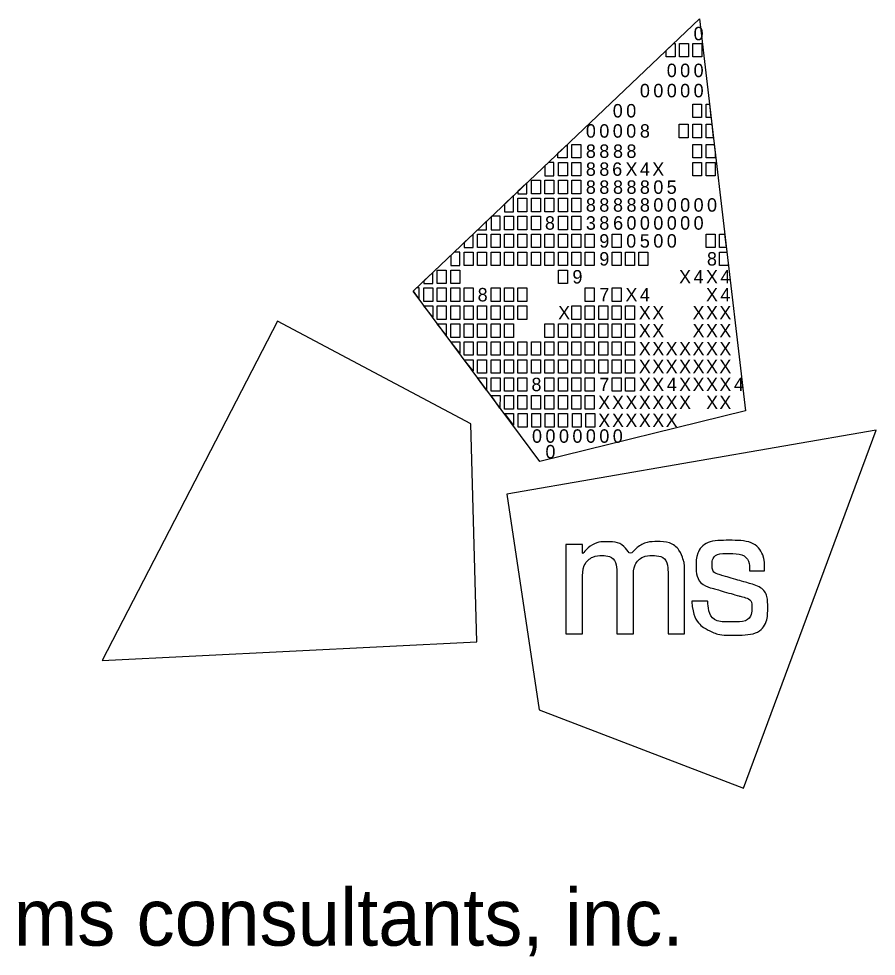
# Model space of a CAD drawing. Extents: x -19 to 34, y 0 to 22.
# Drawn here: x 32.134 to 33.186, y 2.936 to 4.086 of the extents above; entities that cross this region are included whole.
import ezdxf

# ---------------------------------------------------------------- set-up
doc = ezdxf.new("R2010")
doc.units = 0
doc.layers.add('SH_Border', color=7, linetype='Continuous')
doc.layers.add('SH_Data', color=7, linetype='Continuous')

msp = doc.modelspace()

# ---------------------------------------------------------------- linework, layer by layer
at = {"layer": 'SH_Border'}
for p, q in [((32.6175, 3.7519), (32.9688, 4.0861)), ((32.9688, 4.0861), (32.9688, 4.0861)), ((32.9688, 4.0861), (33.0253, 3.6052)), ((32.773, 3.543), (32.6175, 3.7519)), ((33.0253, 3.6052), (32.773, 3.543))]:
    msp.add_line(p, q, dxfattribs=at)
for points in [[(32.9279, 4.0472), (32.9369, 4.0558), (32.9389, 4.0558), (32.9389, 4.0393), (32.9279, 4.0393)], [(32.9444, 4.0558), (32.9554, 4.0558), (32.9554, 4.0393), (32.9444, 4.0393)], [(32.9609, 4.0558), (32.9719, 4.0558), (32.9719, 4.0393), (32.9609, 4.0393)], [(32.9606, 3.9815), (32.9716, 3.9815), (32.9716, 3.965), (32.9606, 3.965)], [(32.9771, 3.9815), (32.9811, 3.9815), (32.983, 3.965), (32.9771, 3.965)], [(32.9441, 3.9567), (32.9551, 3.9567), (32.9551, 3.9402), (32.9441, 3.9402)], [(32.9606, 3.9567), (32.9716, 3.9567), (32.9716, 3.9402), (32.9606, 3.9402)], [(32.9771, 3.9567), (32.984, 3.9567), (32.9859, 3.9402), (32.9771, 3.9402)], [(32.7953, 3.9211), (32.8064, 3.9316), (32.8064, 3.9154), (32.7953, 3.9154)], [(32.8123, 3.9319), (32.8233, 3.9319), (32.8233, 3.9154), (32.8123, 3.9154)], [(32.9606, 3.9319), (32.9716, 3.9319), (32.9716, 3.9154), (32.9606, 3.9154)], [(32.9771, 3.9319), (32.9869, 3.9319), (32.9881, 3.9218), (32.9881, 3.9154), (32.9771, 3.9154)], [(32.7958, 3.9099), (32.8068, 3.9099), (32.8068, 3.8934), (32.7958, 3.8934)], [(32.8123, 3.9099), (32.8233, 3.9099), (32.8233, 3.8934), (32.8123, 3.8934)], [(32.9606, 3.9099), (32.9716, 3.9099), (32.9716, 3.8934), (32.9606, 3.8934)], [(32.9771, 3.9099), (32.9881, 3.9099), (32.9881, 3.8934), (32.9771, 3.8934)], [(32.7627, 3.8879), (32.7737, 3.8879), (32.7737, 3.8714), (32.7627, 3.8714)], [(32.7793, 3.8879), (32.7903, 3.8879), (32.7903, 3.8714), (32.7793, 3.8714)], [(32.7958, 3.8879), (32.8068, 3.8879), (32.8068, 3.8714), (32.7958, 3.8714)], [(32.8123, 3.8879), (32.8233, 3.8879), (32.8233, 3.8714), (32.8123, 3.8714)], [(32.7462, 3.8659), (32.7572, 3.8659), (32.7572, 3.8494), (32.7462, 3.8494)], [(32.7627, 3.8659), (32.7737, 3.8659), (32.7737, 3.8494), (32.7627, 3.8494)], [(32.7793, 3.8659), (32.7903, 3.8659), (32.7903, 3.8494), (32.7793, 3.8494)], [(32.7958, 3.8659), (32.8068, 3.8659), (32.8068, 3.8494), (32.7958, 3.8494)], [(32.8123, 3.8659), (32.8233, 3.8659), (32.8233, 3.8494), (32.8123, 3.8494)], [(32.7297, 3.8439), (32.7407, 3.8439), (32.7407, 3.8273), (32.7297, 3.8273)], [(32.7462, 3.8439), (32.7572, 3.8439), (32.7572, 3.8273), (32.7462, 3.8273)], [(32.7627, 3.8439), (32.7737, 3.8439), (32.7737, 3.8273), (32.7627, 3.8273)], [(32.7958, 3.8439), (32.8068, 3.8439), (32.8068, 3.8273), (32.7958, 3.8273)], [(32.8123, 3.8439), (32.8233, 3.8439), (32.8233, 3.8273), (32.8123, 3.8273)], [(32.6967, 3.8218), (32.7077, 3.8218), (32.7077, 3.8053), (32.6967, 3.8053)], [(32.7132, 3.8218), (32.7242, 3.8218), (32.7242, 3.8053), (32.7132, 3.8053)], [(32.7297, 3.8218), (32.7407, 3.8218), (32.7407, 3.8053), (32.7297, 3.8053)], [(32.7462, 3.8218), (32.7572, 3.8218), (32.7572, 3.8053), (32.7462, 3.8053)], [(32.7627, 3.8218), (32.7737, 3.8218), (32.7737, 3.8053), (32.7627, 3.8053)], [(32.7793, 3.8218), (32.7903, 3.8218), (32.7903, 3.8053), (32.7793, 3.8053)], [(32.7958, 3.8218), (32.8068, 3.8218), (32.8068, 3.8053), (32.7958, 3.8053)], [(32.8123, 3.8218), (32.8233, 3.8218), (32.8233, 3.8053), (32.8123, 3.8053)], [(32.8288, 3.8218), (32.8398, 3.8218), (32.8398, 3.8053), (32.8288, 3.8053)], [(32.8618, 3.8218), (32.8728, 3.8218), (32.8728, 3.8053), (32.8618, 3.8053)], [(32.9771, 3.8218), (32.9881, 3.8218), (32.9881, 3.8053), (32.9771, 3.8053)], [(32.9935, 3.8218), (32.9998, 3.8218), (33.0018, 3.8053), (32.9935, 3.8053)], [(32.6802, 3.7998), (32.6912, 3.7998), (32.6912, 3.7833), (32.6802, 3.7833)], [(32.6967, 3.7998), (32.7077, 3.7998), (32.7077, 3.7833), (32.6967, 3.7833)], [(32.7132, 3.7998), (32.7242, 3.7998), (32.7242, 3.7833), (32.7132, 3.7833)], [(32.7297, 3.7998), (32.7407, 3.7998), (32.7407, 3.7833), (32.7297, 3.7833)], [(32.7462, 3.7998), (32.7572, 3.7998), (32.7572, 3.7833), (32.7462, 3.7833)], [(32.7627, 3.7998), (32.7737, 3.7998), (32.7737, 3.7833), (32.7627, 3.7833)], [(32.7793, 3.7998), (32.7903, 3.7998), (32.7903, 3.7833), (32.7793, 3.7833)], [(32.7958, 3.7998), (32.8068, 3.7998), (32.8068, 3.7833), (32.7958, 3.7833)], [(32.8123, 3.7998), (32.8233, 3.7998), (32.8233, 3.7833), (32.8123, 3.7833)], [(32.8288, 3.7998), (32.8398, 3.7998), (32.8398, 3.7833), (32.8288, 3.7833)], [(32.8618, 3.7998), (32.8728, 3.7998), (32.8728, 3.7833), (32.8618, 3.7833)], [(32.8783, 3.7998), (32.8893, 3.7998), (32.8893, 3.7833), (32.8783, 3.7833)], [(32.8947, 3.7998), (32.9057, 3.7998), (32.9057, 3.7833), (32.8947, 3.7833)], [(32.9935, 3.7998), (33.0024, 3.7998), (33.0044, 3.7833), (32.9935, 3.7833)], [(32.6471, 3.7778), (32.6581, 3.7778), (32.6581, 3.7613), (32.6471, 3.7613)], [(32.6637, 3.7778), (32.6747, 3.7778), (32.6747, 3.7613), (32.6637, 3.7613)], [(32.7958, 3.7778), (32.8068, 3.7778), (32.8068, 3.7613), (32.7958, 3.7613)], [(32.6306, 3.7558), (32.6416, 3.7558), (32.6416, 3.7393), (32.6306, 3.7393)], [(32.6471, 3.7558), (32.6581, 3.7558), (32.6581, 3.7393), (32.6471, 3.7393)], [(32.6637, 3.7558), (32.6747, 3.7558), (32.6747, 3.7393), (32.6637, 3.7393)], [(32.6802, 3.7558), (32.6912, 3.7558), (32.6912, 3.7393), (32.6802, 3.7393)], [(32.7132, 3.7558), (32.7242, 3.7558), (32.7242, 3.7393), (32.7132, 3.7393)], [(32.7297, 3.7558), (32.7407, 3.7558), (32.7407, 3.7393), (32.7297, 3.7393)], [(32.7462, 3.7558), (32.7572, 3.7558), (32.7572, 3.7393), (32.7462, 3.7393)], [(32.8288, 3.7558), (32.8398, 3.7558), (32.8398, 3.7393), (32.8288, 3.7393)], [(32.8618, 3.7558), (32.8728, 3.7558), (32.8728, 3.7393), (32.8618, 3.7393)], [(32.6306, 3.7338), (32.6416, 3.7338), (32.6416, 3.72)], [(32.6471, 3.7338), (32.6581, 3.7338), (32.6581, 3.7173), (32.6471, 3.7173)], [(32.6637, 3.7338), (32.6747, 3.7338), (32.6747, 3.7173), (32.6637, 3.7173)], [(32.6802, 3.7338), (32.6912, 3.7338), (32.6912, 3.7173), (32.6802, 3.7173)], [(32.6967, 3.7338), (32.7077, 3.7338), (32.7077, 3.7173), (32.6967, 3.7173)], [(32.7132, 3.7338), (32.7242, 3.7338), (32.7242, 3.7173), (32.7132, 3.7173)], [(32.7297, 3.7338), (32.7407, 3.7338), (32.7407, 3.7173), (32.7297, 3.7173)], [(32.7462, 3.7338), (32.7572, 3.7338), (32.7572, 3.7173), (32.7462, 3.7173)], [(32.8123, 3.7338), (32.8233, 3.7338), (32.8233, 3.7173), (32.8123, 3.7173)], [(32.8288, 3.7338), (32.8398, 3.7338), (32.8398, 3.7173), (32.8288, 3.7173)], [(32.8453, 3.7338), (32.8563, 3.7338), (32.8563, 3.7173), (32.8453, 3.7173)], [(32.8618, 3.7338), (32.8728, 3.7338), (32.8728, 3.7173), (32.8618, 3.7173)], [(32.8783, 3.7338), (32.8893, 3.7338), (32.8893, 3.7173), (32.8783, 3.7173)], [(32.6471, 3.7117), (32.6581, 3.7117), (32.6581, 3.698)], [(32.6637, 3.7117), (32.6747, 3.7117), (32.6747, 3.6952), (32.6637, 3.6952)], [(32.6802, 3.7117), (32.6912, 3.7117), (32.6912, 3.6952), (32.6802, 3.6952)], [(32.6967, 3.7117), (32.7077, 3.7117), (32.7077, 3.6952), (32.6967, 3.6952)], [(32.7132, 3.7117), (32.7242, 3.7117), (32.7242, 3.6952), (32.7132, 3.6952)], [(32.7297, 3.7117), (32.7407, 3.7117), (32.7407, 3.6952), (32.7297, 3.6952)], [(32.7793, 3.7117), (32.7903, 3.7117), (32.7903, 3.6952), (32.7793, 3.6952)], [(32.7958, 3.7117), (32.8068, 3.7117), (32.8068, 3.6952), (32.7958, 3.6952)], [(32.8123, 3.7117), (32.8233, 3.7117), (32.8233, 3.6952), (32.8123, 3.6952)], [(32.8288, 3.7117), (32.8398, 3.7117), (32.8398, 3.6952), (32.8288, 3.6952)], [(32.8453, 3.7117), (32.8563, 3.7117), (32.8563, 3.6952), (32.8453, 3.6952)], [(32.8618, 3.7117), (32.8728, 3.7117), (32.8728, 3.6952), (32.8618, 3.6952)], [(32.8783, 3.7117), (32.8893, 3.7117), (32.8893, 3.6952), (32.8783, 3.6952)], [(32.6637, 3.6897), (32.6747, 3.6897), (32.6747, 3.676)], [(32.6747, 3.6897), (32.6747, 3.6897), (32.6747, 3.6897)], [(32.6802, 3.6897), (32.6912, 3.6897), (32.6912, 3.6732), (32.6802, 3.6732)], [(32.6967, 3.6897), (32.7077, 3.6897), (32.7077, 3.6732), (32.6967, 3.6732)], [(32.7132, 3.6897), (32.7242, 3.6897), (32.7242, 3.6732), (32.7132, 3.6732)], [(32.7297, 3.6897), (32.7407, 3.6897), (32.7407, 3.6732), (32.7297, 3.6732)], [(32.7462, 3.6897), (32.7572, 3.6897), (32.7572, 3.6732), (32.7462, 3.6732)], [(32.7627, 3.6897), (32.7737, 3.6897), (32.7737, 3.6732), (32.7627, 3.6732)], [(32.7793, 3.6897), (32.7903, 3.6897), (32.7903, 3.6732), (32.7793, 3.6732)], [(32.7958, 3.6897), (32.8068, 3.6897), (32.8068, 3.6732), (32.7958, 3.6732)], [(32.8123, 3.6897), (32.8233, 3.6897), (32.8233, 3.6732), (32.8123, 3.6732)], [(32.8288, 3.6897), (32.8398, 3.6897), (32.8398, 3.6732), (32.8288, 3.6732)], [(32.8453, 3.6897), (32.8563, 3.6897), (32.8563, 3.6732), (32.8453, 3.6732)], [(32.8618, 3.6897), (32.8728, 3.6897), (32.8728, 3.6732), (32.8618, 3.6732)], [(32.8783, 3.6897), (32.8893, 3.6897), (32.8893, 3.6732), (32.8783, 3.6732)], [(32.6802, 3.6677), (32.6912, 3.6677), (32.6912, 3.654)], [(32.6967, 3.6677), (32.7077, 3.6677), (32.7077, 3.6512), (32.6967, 3.6512)], [(32.7132, 3.6677), (32.7242, 3.6677), (32.7242, 3.6512), (32.7132, 3.6512)], [(32.7297, 3.6677), (32.7407, 3.6677), (32.7407, 3.6512), (32.7297, 3.6512)], [(32.7462, 3.6677), (32.7572, 3.6677), (32.7572, 3.6512), (32.7462, 3.6512)], [(32.7627, 3.6677), (32.7737, 3.6677), (32.7737, 3.6512), (32.7627, 3.6512)], [(32.7793, 3.6677), (32.7903, 3.6677), (32.7903, 3.6512), (32.7793, 3.6512)], [(32.7958, 3.6677), (32.8068, 3.6677), (32.8068, 3.6512), (32.7958, 3.6512)], [(32.8123, 3.6677), (32.8233, 3.6677), (32.8233, 3.6512), (32.8123, 3.6512)], [(32.8288, 3.6677), (32.8398, 3.6677), (32.8398, 3.6512), (32.8288, 3.6512)], [(32.8453, 3.6677), (32.8563, 3.6677), (32.8563, 3.6512), (32.8453, 3.6512)], [(32.8618, 3.6677), (32.8728, 3.6677), (32.8728, 3.6512), (32.8618, 3.6512)], [(32.8783, 3.6677), (32.8893, 3.6677), (32.8893, 3.6512), (32.8783, 3.6512)], [(32.7077, 3.6305), (32.6965, 3.6457), (32.7077, 3.6457)], [(32.7132, 3.6457), (32.7242, 3.6457), (32.7242, 3.6292), (32.7132, 3.6292)], [(32.7297, 3.6457), (32.7407, 3.6457), (32.7407, 3.6292), (32.7297, 3.6292)], [(32.7462, 3.6457), (32.7572, 3.6457), (32.7572, 3.6292), (32.7462, 3.6292)], [(32.7793, 3.6457), (32.7903, 3.6457), (32.7903, 3.6292), (32.7793, 3.6292)], [(32.7958, 3.6457), (32.8068, 3.6457), (32.8068, 3.6292), (32.7958, 3.6292)], [(32.8123, 3.6457), (32.8233, 3.6457), (32.8233, 3.6292), (32.8123, 3.6292)], [(32.8288, 3.6457), (32.8398, 3.6457), (32.8398, 3.6292), (32.8288, 3.6292)], [(32.8618, 3.6457), (32.8728, 3.6457), (32.8728, 3.6292), (32.8618, 3.6292)], [(32.8783, 3.6457), (32.8893, 3.6457), (32.8893, 3.6292), (32.8783, 3.6292)], [(32.724, 3.6082), (32.7132, 3.6237), (32.7242, 3.6237)], [(32.7297, 3.6237), (32.7407, 3.6237), (32.7407, 3.6072), (32.7297, 3.6072)], [(32.7462, 3.6237), (32.7572, 3.6237), (32.7572, 3.6072), (32.7462, 3.6072)], [(32.7627, 3.6237), (32.7737, 3.6237), (32.7737, 3.6072), (32.7627, 3.6072)], [(32.7793, 3.6237), (32.7903, 3.6237), (32.7903, 3.6072), (32.7793, 3.6072)], [(32.7958, 3.6237), (32.8068, 3.6237), (32.8068, 3.6072), (32.7958, 3.6072)], [(32.8123, 3.6237), (32.8233, 3.6237), (32.8233, 3.6072), (32.8123, 3.6072)], [(32.8288, 3.6237), (32.8398, 3.6237), (32.8398, 3.6072), (32.8288, 3.6072)], [(32.7302, 3.6017), (32.7407, 3.6017), (32.7408, 3.5875)], [(32.7463, 3.6017), (32.7573, 3.6017), (32.7573, 3.5852), (32.7463, 3.5852)], [(32.763, 3.6017), (32.774, 3.6017), (32.774, 3.5852), (32.763, 3.5852)], [(32.7794, 3.6017), (32.7904, 3.6017), (32.7904, 3.5852), (32.7794, 3.5852)], [(32.796, 3.6017), (32.807, 3.6017), (32.807, 3.5852), (32.796, 3.5852)], [(32.8129, 3.6017), (32.8239, 3.6017), (32.8239, 3.5851), (32.8129, 3.5851)], [(32.8296, 3.6017), (32.8406, 3.6017), (32.8406, 3.5851), (32.8296, 3.5851)]]:
    msp.add_lwpolyline(points, close=True, dxfattribs=at)
for points in [[(32.7903, 3.9099), (32.7836, 3.9099), (32.7793, 3.9058), (32.7793, 3.8934), (32.7903, 3.8934), (32.7903, 3.9099)], [(32.7572, 3.8849), (32.7462, 3.8744), (32.7462, 3.8714), (32.7572, 3.8714), (32.7572, 3.8849)], [(32.7407, 3.8691), (32.7297, 3.8587), (32.7297, 3.8494), (32.7407, 3.8494), (32.7407, 3.8691)], [(32.7242, 3.8439), (32.7141, 3.8439), (32.7132, 3.843), (32.7132, 3.8273), (32.7242, 3.8273), (32.7242, 3.8439)], [(32.7077, 3.8377), (32.6968, 3.8273), (32.7077, 3.8273), (32.7077, 3.8377)], [(32.6912, 3.822), (32.6802, 3.8115), (32.6802, 3.8053), (32.6912, 3.8053), (32.6912, 3.822)], [(32.6747, 3.7998), (32.6679, 3.7998), (32.6637, 3.7958), (32.6637, 3.7833), (32.6747, 3.7833), (32.6747, 3.7998)], [(32.6416, 3.7749), (32.6306, 3.7644), (32.6306, 3.7613), (32.6416, 3.7613), (32.6416, 3.7749)], [(32.6251, 3.7558), (32.6216, 3.7558), (32.6175, 3.7519), (32.6251, 3.7417), (32.6251, 3.7558)], [(32.4512, 3.7149), (32.2359, 3.2988), (32.6956, 3.3215), (32.6884, 3.5892), (32.4512, 3.7149)], [(33.0229, 3.1422), (33.1859, 3.5814), (32.7324, 3.5029), (32.7722, 3.2381), (33.0229, 3.1422)]]:
    msp.add_lwpolyline(points, dxfattribs=at)
for points in [[(32.8048, 3.3315), (32.8048, 3.3315), (32.8048, 3.4409), (32.8048, 3.4409), (32.8048, 3.4409), (32.8255, 3.4409), (32.8255, 3.4409), (32.8255, 3.4409), (32.8255, 3.4297), (32.8255, 3.4297), (32.8346, 3.4399), (32.8457, 3.4445), (32.8555, 3.4445), (32.8688, 3.4445), (32.8791, 3.4372), (32.8837, 3.4266), (32.8915, 3.4381), (32.905, 3.4446), (32.9166, 3.4446), (32.9325, 3.4446), (32.9451, 3.435), (32.9494, 3.4213), (32.9494, 3.4212), (32.9494, 3.4212), (32.9494, 3.4212), (32.9501, 3.419), (32.9506, 3.4172), (32.9506, 3.4071), (32.9506, 3.4071), (32.9506, 3.3314), (32.9506, 3.3314), (32.9506, 3.3314), (32.9303, 3.3314), (32.9303, 3.3314), (32.9303, 3.3314), (32.9303, 3.4048), (32.9303, 3.4048), (32.9303, 3.4201), (32.9219, 3.4274), (32.911, 3.4274), (32.8995, 3.4274), (32.8879, 3.4171), (32.8879, 3.4001), (32.8879, 3.4001), (32.8879, 3.3315), (32.8879, 3.3315), (32.8879, 3.3315), (32.8674, 3.3315), (32.8674, 3.3315), (32.8674, 3.3315), (32.8674, 3.4059), (32.8674, 3.4059), (32.8674, 3.4203), (32.8588, 3.4274), (32.8496, 3.4274), (32.8384, 3.4274), (32.8254, 3.417), (32.8254, 3.3962), (32.8254, 3.3962), (32.8254, 3.3315), (32.8254, 3.3315), (32.8254, 3.3315), (32.8048, 3.3315), (32.8048, 3.3315)], [(32.9595, 3.3709), (32.9595, 3.3709), (32.9595, 3.3717), (32.9595, 3.3717), (32.9595, 3.3717), (32.9603, 3.3717), (32.9603, 3.3717), (32.9603, 3.3717), (32.9783, 3.3717), (32.9783, 3.3717), (32.9783, 3.3717), (32.9789, 3.3717), (32.9789, 3.3717), (32.9789, 3.3717), (32.979, 3.371), (32.979, 3.371), (32.9803, 3.3554), (32.9887, 3.346), (33.009, 3.346), (33.0273, 3.346), (33.0333, 3.3554), (33.0333, 3.3631), (33.0333, 3.3732), (33.0256, 3.3758), (33.0175, 3.378), (33.0175, 3.378), (32.987, 3.3867), (32.987, 3.3867), (32.972, 3.3909), (32.9648, 3.4019), (32.9648, 3.4142), (32.9648, 3.4303), (32.9768, 3.4462), (33.0052, 3.4462), (33.0348, 3.4462), (33.0489, 3.4285), (33.0489, 3.4095), (33.0489, 3.4095), (33.0489, 3.4087), (33.0489, 3.4087), (33.0489, 3.4087), (33.0482, 3.4087), (33.0482, 3.4087), (33.0482, 3.4087), (33.0312, 3.4087), (33.0312, 3.4087), (33.0312, 3.4087), (33.0305, 3.4087), (33.0305, 3.4087), (33.0305, 3.4087), (33.0305, 3.4094), (33.0305, 3.4094), (33.0301, 3.4208), (33.0226, 3.43), (33.0056, 3.43), (32.9891, 3.43), (32.9843, 3.4218), (32.9843, 3.4157), (32.9843, 3.4108), (32.9869, 3.4059), (32.9959, 3.4033), (32.9959, 3.4033), (33.0255, 3.3948), (33.0255, 3.3948), (33.0462, 3.3889), (33.0527, 3.3777), (33.0527, 3.3639), (33.0527, 3.3462), (33.041, 3.3298), (33.0087, 3.3298), (32.9952, 3.3298), (32.9877, 3.3321), (32.9823, 3.3348), (32.969, 3.3414), (32.9609, 3.3536), (32.9595, 3.3709)]]:
    msp.add_open_spline(points, degree=3, dxfattribs=at)
at = {"layer": 'SH_Data'}
msp.add_line((32.75, 3.5), (32.75, 3.5), dxfattribs=at)

# ---------------------------------------------------------------- texts
at = {"layer": 'SH_Border'}
for s, height, p in [('0', 0.0165, (32.9617, 4.0597)), ('0', 0.0165, (32.9288, 4.0145)), ('0', 0.0165, (32.9452, 4.0145)), ('0', 0.0165, (32.9617, 4.0145)), ('0', 0.0165, (32.8958, 3.9897)), ('0', 0.0165, (32.9123, 3.9897)), ('0', 0.0165, (32.9288, 3.9897)), ('0', 0.0165, (32.9452, 3.9897)), ('0', 0.0165, (32.9617, 3.9897)), ('0', 0.0165, (32.8625, 3.965)), ('0', 0.0165, (32.879, 3.965)), ('0', 0.0165, (32.8295, 3.9402)), ('0', 0.0165, (32.846, 3.9402)), ('0', 0.0165, (32.8625, 3.9402)), ('0', 0.0165, (32.879, 3.9402)), ('8', 0.0165, (32.8958, 3.9402)), ('8', 0.0165, (32.8295, 3.9154)), ('8', 0.0165, (32.846, 3.9154)), ('8', 0.0165, (32.8628, 3.9154)), ('8', 0.0165, (32.8793, 3.9154)), ('8', 0.0165, (32.8295, 3.8934)), ('8', 0.0165, (32.846, 3.8934)), ('6', 0.0165, (32.8618, 3.8934)), ('X', 0.0165, (32.8781, 3.8934)), ('4', 0.0165, (32.8958, 3.8934)), ('X', 0.0165, (32.911, 3.8934)), ('8', 0.0165, (32.8295, 3.8713)), ('8', 0.0165, (32.846, 3.8713)), ('8', 0.0165, (32.8628, 3.8713)), ('8', 0.0165, (32.8794, 3.8713)), ('8', 0.0165, (32.8958, 3.8713)), ('0', 0.0165, (32.9123, 3.8713)), ('5', 0.0165, (32.9287, 3.8713)), ('8', 0.0165, (32.8295, 3.8494)), ('8', 0.0165, (32.846, 3.8494)), ('8', 0.0165, (32.8628, 3.8494)), ('8', 0.0165, (32.8794, 3.8494)), ('8', 0.0165, (32.8958, 3.8494)), ('0', 0.0165, (32.9123, 3.8494)), ('0', 0.0165, (32.9288, 3.8494)), ('0', 0.0165, (32.9452, 3.8494)), ('0', 0.0165, (32.9617, 3.8494)), ('0', 0.0165, (32.9782, 3.8494)), ('8', 0.0165, (32.7793, 3.8273)), ('3', 0.0165, (32.8295, 3.8273)), ('8', 0.0165, (32.846, 3.8273)), ('6', 0.0165, (32.8629, 3.8273)), ('0', 0.0165, (32.8793, 3.8273)), ('0', 0.0165, (32.8958, 3.8273)), ('0', 0.0165, (32.9123, 3.8273)), ('0', 0.0165, (32.9288, 3.8273)), ('0', 0.0165, (32.9452, 3.8273)), ('0', 0.0165, (32.9617, 3.8273)), ('9', 0.0165, (32.846, 3.8053)), ('0', 0.0165, (32.879, 3.8053)), ('5', 0.0165, (32.8957, 3.8053)), ('0', 0.0165, (32.9123, 3.8053)), ('0', 0.0165, (32.9288, 3.8053)), ('9', 0.0165, (32.846, 3.7833)), ('8', 0.0165, (32.9781, 3.7833)), ('9', 0.0165, (32.813, 3.7613)), ('X', 0.0165, (32.9439, 3.7613)), ('4', 0.0165, (32.9617, 3.7613)), ('X', 0.0165, (32.9769, 3.7613)), ('4', 0.0165, (32.9946, 3.7613)), ('8', 0.0165, (32.6967, 3.7393)), ('7', 0.0165, (32.846, 3.7393)), ('X', 0.0165, (32.8781, 3.7393)), ('4', 0.0165, (32.8958, 3.7393)), ('X', 0.0165, (32.9769, 3.7393)), ('4', 0.0165, (32.9946, 3.7393)), ('X', 0.0165, (32.7955, 3.7173)), ('X', 0.0165, (32.8945, 3.7173)), ('X', 0.0165, (32.911, 3.7173)), ('X', 0.0165, (32.9604, 3.7173)), ('X', 0.0165, (32.9769, 3.7173)), ('X', 0.0165, (32.9933, 3.7173)), ('X', 0.0165, (32.8945, 3.6952)), ('X', 0.0165, (32.911, 3.6952)), ('X', 0.0165, (32.9604, 3.6952)), ('X', 0.0165, (32.9769, 3.6952)), ('X', 0.0165, (32.9933, 3.6952)), ('X', 0.0165, (32.8945, 3.6732)), ('X', 0.0165, (32.911, 3.6732)), ('X', 0.0165, (32.9274, 3.6732)), ('X', 0.0165, (32.9439, 3.6732)), ('X', 0.0165, (32.9604, 3.6732)), ('X', 0.0165, (32.9769, 3.6732)), ('X', 0.0165, (32.9933, 3.6732)), ('X', 0.0165, (32.8945, 3.6512)), ('X', 0.0165, (32.911, 3.6512)), ('X', 0.0165, (32.9274, 3.6512)), ('X', 0.0165, (32.9439, 3.6512)), ('X', 0.0165, (32.9604, 3.6512)), ('X', 0.0165, (32.9769, 3.6512)), ('X', 0.0165, (32.9933, 3.6512)), ('8', 0.0165, (32.7627, 3.6292)), ('7', 0.0165, (32.846, 3.6292)), ('X', 0.0165, (32.8945, 3.6292)), ('X', 0.0165, (32.911, 3.6292)), ('4', 0.0165, (32.9288, 3.6292)), ('X', 0.0165, (32.9439, 3.6292)), ('X', 0.0165, (32.9604, 3.6292)), ('X', 0.0165, (32.9769, 3.6292)), ('X', 0.0165, (32.9933, 3.6292)), ('4', 0.0165, (33.0111, 3.6292)), ('X', 0.0165, (32.8447, 3.6072)), ('X', 0.0165, (32.8616, 3.6072)), ('X', 0.0165, (32.878, 3.6072)), ('X', 0.0165, (32.8945, 3.6072)), ('X', 0.0165, (32.911, 3.6072)), ('X', 0.0165, (32.9274, 3.6072)), ('X', 0.0165, (32.9439, 3.6072)), ('X', 0.0165, (32.9771, 3.6072)), ('X', 0.0165, (32.9933, 3.6072)), ('X', 0.0165, (32.8447, 3.5851)), ('X', 0.0165, (32.8616, 3.5851)), ('X', 0.0165, (32.878, 3.5851)), ('X', 0.0165, (32.8945, 3.5851)), ('X', 0.0165, (32.911, 3.5851)), ('X', 0.0165, (32.9274, 3.5851)), ('0', 0.0165, (32.7634, 3.5659)), ('0', 0.0165, (32.7799, 3.5659)), ('0', 0.0165, (32.7965, 3.5659)), ('0', 0.0165, (32.813, 3.5659)), ('0', 0.0165, (32.8295, 3.5659)), ('0', 0.0165, (32.846, 3.5659)), ('0', 0.0165, (32.8625, 3.5659)), ('0', 0.0165, (32.7799, 3.5467)), ('ms consultants, inc.', 0.07, (32.1273, 2.9489))]:
    msp.add_text(s, height=height, rotation=360, dxfattribs=at).set_placement(p)

doc.saveas('drawing.dxf')
